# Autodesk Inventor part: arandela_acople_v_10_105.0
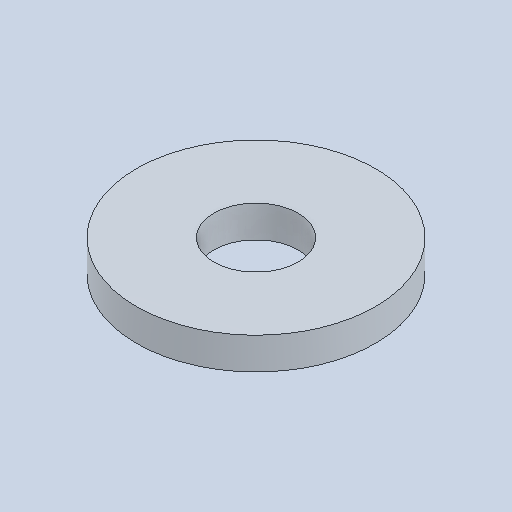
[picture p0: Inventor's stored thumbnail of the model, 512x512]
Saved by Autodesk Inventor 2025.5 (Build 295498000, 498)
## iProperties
Created: 2026-10
Part Number: arandela_acople_v_10_105.0
Material: Genérico
Document SubType Name: Modeling
Designer: Luis M
Density: 1 g/cm^3
Appearance: Valor por defecto
Author: Luis M
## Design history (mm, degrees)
feature "Base1"
node "Sólido1"
